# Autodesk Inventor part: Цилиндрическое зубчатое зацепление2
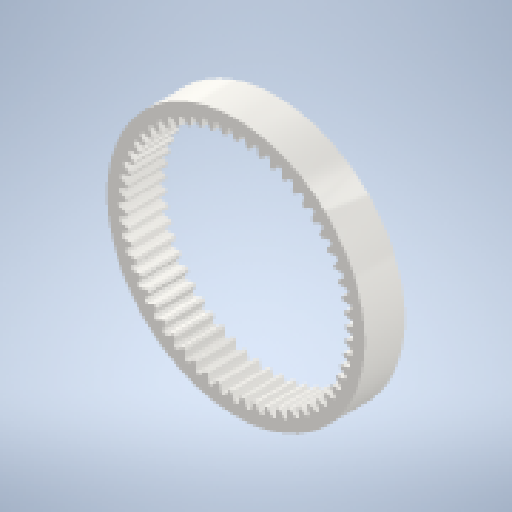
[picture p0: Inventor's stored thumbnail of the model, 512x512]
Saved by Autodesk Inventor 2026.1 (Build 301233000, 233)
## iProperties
Created: 2026-01
Part Number: Цилиндрическое зубчатое зацепление2
Material: Steel
Document SubType Name: Modeling
Designer: Yury Melnikov
Categories: <?xml version="1.0" encoding="UTF-16"?> <MemberInstance><Categories><FamilyTemplate><FamilyTemplateParameter ValueType="xs:double" Id="1" ObjectReferenceKey="da
Density: 1 g/cm^3
Appearance: Steel
CustomPartVersion: 1
Author: Yury Melnikov
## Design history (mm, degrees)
sketch "Sketch1"
  geometry: C1 r 64.433 at (0, 0)
  constraints: 1 centre point
  dimensions: "d0" = 128.86539 diameter of C1 (= 1.1 x da_df)
extrude "Extrusion1" new body sketch "Sketch1" distance "d1" = 20 (= da_b); taper "d2" = 0 deg
workplane "Work Plane2"
feature "Средний диаметр" dims "d4" = 10, "d5" = 0
workplane "Work Plane8"
workplane "Work Plane9"
feature "Цилиндрическое зубчатое зацепление" dims "da_b" = 20, "da_d" = 114, "da_z" = 570, "da_aw" = 32.28494, "da_da" = 109.62054, "da_df" = 117.15035, "da_dw" = 108.24951, "da_z2" = 230, "da_beta" = 0, "da_lefttooth" = 0, "da_righttooth" = 0, "da_straighttooth" = 10
body "Solid1"
sketch "Sketch2"
  geometry: C1 r 64.433 at (0, 0) reference; C2 r 57 at (0, 0)
  constraints: 1 centre point, 1 coincident
  dimensions: "d3" = 114 diameter of C2 (= da_d)
body "Srf1"
other parameters: "d16" = 32.28494 (= da_aw), "d17" = 0, "d34" = 0.55116 (computed from da_z), "d39" = 0, "d45" = 0, "d47" = 32.28494 (= da_aw), "d50" = 0, "d51" = 0, "d52" = 32.28494 (= da_aw)
